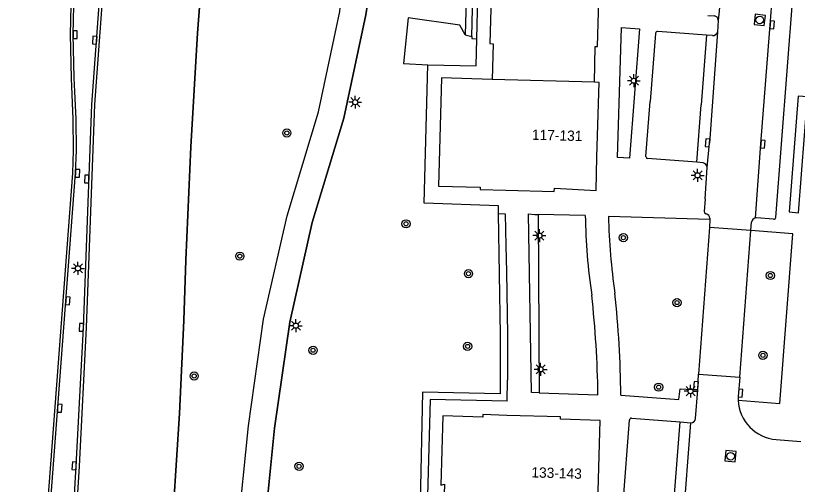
# Model space of a CAD drawing. Extents: x 132573 to 132944, y 398226 to 398676.
# Drawn here: x 132750.7 to 132826.8, y 398341.8 to 398387.4 of the extents above; entities that cross this region are included whole.
import ezdxf

# ---------------------------------------------------------------- set-up
doc = ezdxf.new("R2010")
doc.units = 0
for name, color, linetype in [('gg-anno-huisnummerreeks BGT', 7, 'Continuous'), ('gg-bbg-hoofdgebouw', 7, 'Continuous'), ('gg-bbg-tussenscheiding', 7, 'Continuous'), ('gg-knt-verharding', 7, 'Continuous'), ('gg-knt-verharding nz', 7, 'Continuous'), ('gt-grn-groengrens', 7, 'Continuous'), ('gt-symb-boom', 7, 'Continuous'), ('gt-symb-kolk', 7, 'Continuous'), ('gt-symb-lichtmast', 7, 'Continuous'), ('gt-symb-rioolschacht', 7, 'Continuous'), ('ir-asfa-asfalt arcering', 7, 'Continuous'), ('ir-asfa-asfalt rood', 7, 'Continuous')]:
    doc.layers.add(name, color=color, linetype=linetype)

msp = doc.modelspace()

# ---------------------------------------------------------------- linework, layer by layer
at = {"layer": 'gg-bbg-hoofdgebouw'}
msp.add_line((132807.26, 398337.57), (132807.56, 398348.04), dxfattribs=at)
for points in [[(132797.46, 398396.224), (132797.36, 398392.58), (132797.05, 398392.59), (132796.83, 398384.66), (132797.17, 398384.65), (132797.05, 398381.18)], [(132807.01, 398380.9), (132807.1, 398384.39), (132807.32, 398384.37), (132807.53, 398392.27), (132807.3, 398392.27), (132807.41, 398395.925)], [(132797.05, 398381.18), (132792.13, 398381.32), (132791.86, 398370.81), (132795.91, 398370.7), (132795.91, 398370.48), (132798.404, 398370.414)], [(132807.26, 398373.66), (132807.46, 398380.89), (132807.01, 398380.9)], [(132798.404, 398370.414), (132803.11, 398370.29), (132803.12, 398370.62), (132807.17, 398370.38), (132807.26, 398373.66)], [(132798.495, 398348.532), (132796.16, 398348.6), (132796.15, 398348.37), (132792.26, 398348.48), (132792.06, 398341.76), (132792.42, 398341.84), (132792.311, 398338)], [(132807.56, 398348.04), (132803.7, 398348.15), (132803.71, 398348.38), (132798.495, 398348.532)]]:
    msp.add_lwpolyline(points, dxfattribs=at)
at = {"layer": 'gg-bbg-tussenscheiding'}
msp.add_line((132807.01, 398380.9), (132797.05, 398381.18), dxfattribs=at)
at = {"layer": 'gg-knt-verharding'}
for p, q in [((132824.644, 398367.756), (132829.363, 398428.64)), ((132795.57, 398385.14), (132796.539, 398421.759)), ((132818.043, 398387.401), (132818.682, 398387.358)), ((132819.054, 398386.947), (132818.989, 398385.781)), ((132809.271, 398373.602), (132809.632, 398386.223)), ((132809.632, 398386.223), (132811.402, 398386.088)), ((132811.402, 398386.088), (132810.431, 398373.529)), ((132817.926, 398385.469), (132813.19, 398385.842)), ((132812.962, 398385.658), (132812.446, 398379.041)), ((132818.499, 398385.436), (132817.926, 398385.469)), ((132812.027, 398373.697), (132812.446, 398379.041)), ((132810.431, 398373.529), (132809.271, 398373.602)), ((132816.978, 398373.126), (132812.187, 398373.51)), ((132817.583, 398373.072), (132816.978, 398373.126)), ((132817.78, 398369.588), (132817.983, 398372.624)), ((132797.67, 398368.15), (132798.345, 398368.131)), ((132798.345, 398368.131), (132798.401, 398365.021)), ((132801.228, 398368.052), (132801.528, 398368.044)), ((132806.126, 398367.948), (132801.528, 398368.044)), ((132818.243, 398367.565), (132808.378, 398367.87)), ((132818.25, 398367.692), (132818.243, 398367.565)), ((132818.243, 398367.565), (132818.202, 398366.784)), ((132822.237, 398366.508), (132822.3, 398367.313)), ((132818.202, 398366.784), (132817.142, 398352.535)), ((132822.236, 398366.489), (132818.202, 398366.784)), ((132821.154, 398352.239), (132822.236, 398366.489)), ((132822.236, 398366.489), (132822.237, 398366.508)), ((132798.401, 398365.021), (132798.447, 398362.475)), ((132798.551, 398354.366), (132798.543, 398351.947)), ((132817.062, 398351.025), (132817.142, 398352.535)), ((132817.142, 398352.535), (132821.154, 398352.239)), ((132798.535, 398349.903), (132798.543, 398351.947)), ((132816.848, 398348.236), (132817.062, 398351.025)), ((132801.63, 398350.714), (132807.359, 398350.534)), ((132808.606, 398324.128), (132810.414, 398348.064)), ((132810.612, 398348.258), (132815.337, 398347.889)), ((132815.337, 398347.889), (132816.386, 398347.808)), ((132824.691, 398346.18), (132827.083, 398345.999))]:
    msp.add_line(p, q, dxfattribs=at)
for points in [[(132753.3, 398299.864), (132755.636, 398329.162), (132756.237, 398337.37), (132756.613, 398343.619), (132757.317, 398357.072), (132758.127, 398378.751), (132760.776, 398414.868), (132761.889, 398429.296), (132764.039, 398459.154), (132765.586, 398479.069)], [(132751.083, 398300.042), (132756.534, 398372.062), (132756.626, 398374.274), (132756.591, 398377.31), (132756.41, 398381.327), (132756.304, 398385.531), (132756.415, 398389.799), (132756.753, 398395.79), (132758.744, 398414.418), (132759.507, 398422.619), (132763.174, 398471.173), (132763.665, 398478.479)], [(132769.561, 398303.283), (132769.399, 398307.62), (132769.421, 398308.718), (132770.341, 398314.976), (132771.354, 398325.693), (132772.297, 398336.945), (132773.356, 398347.504), (132774.813, 398357.892), (132777.118, 398367.913), (132780.159, 398378.036), (132782.25, 398387.791), (132782.424, 398389.763), (132784.201, 398412.055), (132784.507, 398417.133), (132784.588, 398421.772), (132784.51, 398423.836), (132783.085, 398433.113), (132780.793, 398443.311), (132779.879, 398448.461), (132779.385, 398453.816)], [(132771.98, 398303.047), (132771.788, 398306.193), (132771.845, 398308.224), (132772.853, 398314.758), (132773.898, 398325.679), (132774.85, 398336.902), (132775.884, 398347.278), (132777.371, 398357.589), (132779.553, 398367.268), (132782.624, 398377.407), (132784.767, 398387.448), (132785.107, 398389.577), (132786.805, 398411.719), (132787.031, 398417.139), (132787.129, 398421.145)], [(132764.017, 398309.742), (132766.081, 398339.639), (132766.643, 398348.698), (132767.065, 398357.764), (132767.263, 398363.623), (132767.769, 398374.645), (132768.407, 398385.661), (132768.845, 398391.611)], [(132790.8, 398382.61), (132795.5, 398382.49), (132795.57, 398385.14)], [(132797.67, 398368.15), (132797.67, 398368.88), (132790.45, 398369.16), (132790.8, 398382.61)], [(132827.73, 398379.475), (132826.825, 398379.543), (132825.967, 398368.308)], [(132825.967, 398368.308), (132826.866, 398368.221), (132827.73, 398379.475)], [(132817.78, 398369.588), (132817.688, 398368.332), (132817.72, 398368.202), (132817.865, 398368.108)], [(132801.63, 398350.714), (132800.902, 398350.736), (132800.588, 398368.117), (132801.228, 398368.052)], [(132824.441, 398367.606), (132822.779, 398367.727), (132822.678, 398367.717)], [(132820.996, 398349.994), (132825.052, 398349.675), (132826.302, 398366.166), (132822.237, 398366.508)], [(132798.447, 398362.475), (132798.558, 398356.362), (132798.551, 398354.366)], [(132821.154, 398352.239), (132820.995, 398350.351), (132820.996, 398349.994)], [(132809.584, 398350.479), (132815.232, 398350.056), (132815.366, 398351.117), (132817.062, 398351.025)], [(132798.535, 398349.903), (132791.03, 398350.08), (132789.91, 398309.15), (132789.475, 398309.165)]]:
    msp.add_lwpolyline(points, dxfattribs=at)
for centre, radius, start, end in [((132818.609, 398386.918), 0.445, 3.66888, 80.62821), ((132813.14, 398385.671), 0.178, 73.54897, 184.25931), ((132818.492, 398385.967), 0.531, 270.80775, 339.48959), ((132812.215, 398373.696), 0.188, 179.64679, 261.4548), ((132817.479, 398372.576), 0.507, 5.41411, 78.10649), ((132865.478, 398368.846), 59.359, 180.86713, 188.37361), ((132871.93, 398369.413), 63.571, 181.39076, 188.13525), ((132817.783, 398367.646), 0.469, 5.62162, 79.94571), ((132822.77, 398367.252), 0.474, 101.1828, 172.62575), ((132824.479, 398367.767), 0.165, 256.70705, 356.21555), ((132704.278, 398348.915), 103.094, 0.89973, 6.28541), ((132704.129, 398349.258), 105.462, 0.66357, 6.07408), ((132825.011, 398350.187), 4.02, 182.75101, 265.43313), ((132810.609, 398348.063), 0.195, 89.01682, 179.81392), ((132816.401, 398348.255), 0.448, 268.11982, 357.50465)]:
    msp.add_arc(centre, radius, start, end, dxfattribs=at)
at = {"layer": 'gg-knt-verharding nz'}
for p, q in [((132817.926, 398385.469), (132817.4, 398378.71)), ((132818.989, 398385.781), (132818.215, 398374.995)), ((132816.978, 398373.126), (132817.4, 398378.71)), ((132817.983, 398372.624), (132818.215, 398374.995)), ((132813.517, 398323.528), (132815.337, 398347.889))]:
    msp.add_line(p, q, dxfattribs=at)
for points in [[(132822.678, 398367.717), (132823.197, 398374.914), (132825.235, 398400.952), (132826.312, 398415.022), (132826.738, 398420.929)], [(132819.912, 398397.905), (132819.149, 398387.801), (132819.054, 398386.947)], [(132814.506, 398323.009), (132815.632, 398338.083), (132816.386, 398347.808)]]:
    msp.add_lwpolyline(points, dxfattribs=at)
at = {"layer": 'gt-grn-groengrens'}
for p, q in [((132794.432, 398385.527), (132795.09, 398385.365)), ((132801.528, 398368.044), (132801.63, 398350.714)), ((132790.288, 398350.798), (132789.475, 398309.165))]:
    msp.add_line(p, q, dxfattribs=at)
for points in [[(132795.09, 398385.365), (132795.925, 398420.614), (132795.446, 398420.602), (132794.432, 398385.527)], [(132794.432, 398385.527), (132793.908, 398386.468), (132788.879, 398387.168), (132788.434, 398382.726), (132790.8, 398382.61)], [(132795.09, 398385.365), (132795.085, 398385.153), (132795.57, 398385.14)], [(132797.67, 398368.15), (132797.645, 398368.15), (132797.858, 398356.357), (132797.838, 398350.62), (132790.288, 398350.798)]]:
    msp.add_lwpolyline(points, dxfattribs=at)
at = {"layer": 'gt-symb-boom'}
for centre, radius in [((132777.095, 398375.978), 0.4), ((132777.095, 398375.978), 0.2), ((132788.685, 398367.144), 0.4), ((132788.685, 398367.144), 0.2), ((132809.831, 398365.806), 0.4), ((132809.831, 398365.806), 0.2), ((132772.519, 398364.006), 0.4), ((132772.519, 398364.006), 0.2), ((132794.76, 398362.3), 0.4), ((132794.76, 398362.3), 0.2), ((132824.122, 398362.126), 0.4), ((132824.122, 398362.126), 0.2), ((132815.05, 398359.491), 0.4), ((132815.05, 398359.491), 0.2), ((132794.673, 398355.232), 0.4), ((132794.673, 398355.232), 0.2), ((132779.648, 398354.856), 0.4), ((132779.648, 398354.856), 0.2), ((132823.399, 398354.369), 0.4), ((132823.399, 398354.369), 0.2), ((132768.079, 398352.353), 0.4), ((132768.079, 398352.353), 0.2), ((132813.257, 398351.271), 0.4), ((132813.257, 398351.271), 0.2), ((132778.283, 398343.574), 0.4), ((132778.283, 398343.574), 0.2)]:
    msp.add_circle(centre, radius, dxfattribs=at)
at = {"layer": 'gt-symb-kolk'}
for points in [[(132824.109, 398386.516), (132824.08, 398386.142), (132824.478, 398386.111), (132824.537, 398386.858), (132824.138, 398386.89), (132824.109, 398386.516)], [(132756.304, 398385.531), (132756.294, 398385.156), (132756.694, 398385.146), (132756.714, 398385.895), (132756.314, 398385.906), (132756.304, 398385.531)], [(132758.608, 398384.987), (132758.637, 398385.361), (132758.238, 398385.392), (132758.18, 398384.644), (132758.579, 398384.613), (132758.608, 398384.987)], [(132818.215, 398374.995), (132818.242, 398375.369), (132817.843, 398375.398), (132817.789, 398374.65), (132818.188, 398374.621), (132818.215, 398374.995)], [(132823.197, 398374.914), (132823.17, 398374.54), (132823.569, 398374.511), (132823.623, 398375.259), (132823.224, 398375.288), (132823.197, 398374.914)], [(132756.534, 398372.062), (132756.519, 398371.687), (132756.918, 398371.671), (132756.949, 398372.42), (132756.549, 398372.437), (132756.534, 398372.062)], [(132757.836, 398371.497), (132757.848, 398371.872), (132757.448, 398371.885), (132757.424, 398371.135), (132757.824, 398371.122), (132757.836, 398371.497)], [(132755.59, 398359.675), (132755.562, 398359.301), (132755.961, 398359.271), (132756.017, 398360.019), (132755.618, 398360.049), (132755.59, 398359.675)], [(132757.317, 398357.072), (132757.336, 398357.446), (132756.937, 398357.467), (132756.898, 398356.718), (132757.298, 398356.698), (132757.317, 398357.072)], [(132817.092, 398351.416), (132817.121, 398351.79), (132816.722, 398351.82), (132816.665, 398351.073), (132817.063, 398351.042), (132817.092, 398351.416)], [(132821.025, 398350.707), (132820.994, 398350.333), (132821.392, 398350.3), (132821.455, 398351.047), (132821.056, 398351.081), (132821.025, 398350.707)], [(132754.801, 398349.229), (132754.773, 398348.855), (132755.172, 398348.825), (132755.228, 398349.573), (132754.829, 398349.603), (132754.801, 398349.229)], [(132756.613, 398343.619), (132756.636, 398343.993), (132756.236, 398344.017), (132756.191, 398343.269), (132756.59, 398343.245), (132756.613, 398343.619)]]:
    msp.add_lwpolyline(points, dxfattribs=at)
at = {"layer": 'gt-symb-lichtmast'}
for p, q in [((132810.674, 398381.228), (132810.409, 398381.493)), ((132810.851, 398381.301), (132810.851, 398381.676)), ((132811.028, 398381.228), (132811.293, 398381.493)), ((132810.601, 398381.051), (132810.226, 398381.051)), ((132810.674, 398380.874), (132810.409, 398380.609)), ((132810.851, 398380.801), (132810.851, 398380.426)), ((132811.293, 398380.609), (132811.028, 398380.874)), ((132811.101, 398381.051), (132811.476, 398381.051)), ((132783.57, 398379.144), (132783.305, 398379.409)), ((132783.747, 398379.217), (132783.747, 398379.592)), ((132783.924, 398379.144), (132784.189, 398379.409)), ((132783.497, 398378.967), (132783.122, 398378.967)), ((132783.57, 398378.79), (132783.305, 398378.525)), ((132783.747, 398378.717), (132783.747, 398378.342)), ((132784.189, 398378.525), (132783.924, 398378.79)), ((132783.997, 398378.967), (132784.372, 398378.967)), ((132816.871, 398372.035), (132816.606, 398372.3)), ((132817.048, 398372.108), (132817.048, 398372.483)), ((132817.225, 398372.035), (132817.49, 398372.3)), ((132816.798, 398371.858), (132816.423, 398371.858)), ((132816.871, 398371.681), (132816.606, 398371.416)), ((132817.048, 398371.608), (132817.048, 398371.233)), ((132817.49, 398371.416), (132817.225, 398371.681)), ((132817.298, 398371.858), (132817.673, 398371.858)), ((132801.483, 398366.177), (132801.218, 398366.442)), ((132801.66, 398366.25), (132801.66, 398366.625)), ((132801.837, 398366.177), (132802.102, 398366.442)), ((132801.41, 398366), (132801.035, 398366)), ((132801.483, 398365.823), (132801.218, 398365.558)), ((132801.66, 398365.75), (132801.66, 398365.375)), ((132802.102, 398365.558), (132801.837, 398365.823)), ((132801.91, 398366), (132802.285, 398366)), ((132756.601, 398362.995), (132756.336, 398363.26)), ((132756.778, 398363.068), (132756.778, 398363.443)), ((132756.955, 398362.995), (132757.22, 398363.26)), ((132756.528, 398362.818), (132756.153, 398362.818)), ((132756.601, 398362.641), (132756.336, 398362.376)), ((132756.778, 398362.568), (132756.778, 398362.193)), ((132757.22, 398362.376), (132756.955, 398362.641)), ((132757.028, 398362.818), (132757.403, 398362.818)), ((132777.975, 398357.495), (132777.975, 398357.87)), ((132777.725, 398357.245), (132777.35, 398357.245)), ((132777.798, 398357.422), (132777.533, 398357.687)), ((132777.798, 398357.068), (132777.533, 398356.803)), ((132777.975, 398356.995), (132777.975, 398356.62)), ((132778.152, 398357.422), (132778.417, 398357.687)), ((132778.417, 398356.803), (132778.152, 398357.068)), ((132778.225, 398357.245), (132778.6, 398357.245)), ((132801.601, 398353.177), (132801.336, 398353.442)), ((132801.778, 398353.25), (132801.778, 398353.625)), ((132801.955, 398353.177), (132802.22, 398353.442)), ((132801.528, 398353), (132801.153, 398353)), ((132801.601, 398352.823), (132801.336, 398352.558)), ((132801.778, 398352.75), (132801.778, 398352.375)), ((132802.22, 398352.558), (132801.955, 398352.823)), ((132802.028, 398353), (132802.403, 398353)), ((132816.12, 398350.88), (132815.745, 398350.88)), ((132816.193, 398351.057), (132815.928, 398351.322)), ((132816.37, 398351.13), (132816.37, 398351.505)), ((132816.547, 398351.057), (132816.812, 398351.322)), ((132816.62, 398350.88), (132816.995, 398350.88)), ((132816.193, 398350.703), (132815.928, 398350.438)), ((132816.37, 398350.63), (132816.37, 398350.255)), ((132816.812, 398350.438), (132816.547, 398350.703))]:
    msp.add_line(p, q, dxfattribs=at)
for centre in [(132810.851, 398381.051), (132783.747, 398378.967), (132817.048, 398371.858), (132801.66, 398366), (132756.778, 398362.818), (132777.975, 398357.245), (132801.778, 398353), (132816.37, 398350.88)]:
    msp.add_circle(centre, 0.25, dxfattribs=at)
at = {"layer": 'gt-symb-rioolschacht'}
for points in [[(132823.53, 398386.408), (132823.655, 398387.401), (132822.662, 398387.526), (132822.537, 398386.533)], [(132819.706, 398344.109), (132820.701, 398344.006), (132820.804, 398345.001), (132819.809, 398345.104)]]:
    msp.add_lwpolyline(points, close=True, dxfattribs=at)
for centre in [(132823.096, 398386.967), (132820.255, 398344.555)]:
    msp.add_circle(centre, 0.375, dxfattribs=at)
at = {"layer": 'ir-asfa-asfalt arcering'}
for points in [[(132756.536, 398337.35), (132756.913, 398343.602), (132757.617, 398357.059), (132758.427, 398378.734), (132761.075, 398414.845), (132762.188, 398429.274), (132764.338, 398459.132)], [(132772.884, 398446.484), (132769.392, 398399.047), (132768.845, 398391.611), (132768.407, 398385.661), (132767.769, 398374.645), (132767.263, 398363.623), (132767.065, 398357.764), (132766.643, 398348.698), (132766.081, 398339.639)], [(132745.571, 398382.431), (132746.483, 398387.846), (132747.325, 398393.731), (132756.281, 398392.746), (132756.115, 398389.811), (132756.004, 398385.531), (132756.11, 398381.316), (132756.291, 398377.302), (132756.326, 398374.279), (132756.234, 398372.08), (132750.784, 398300.065), (132750.784, 398300.061), (132750.599, 398297.174), (132750.599, 398297.173), (132737.591, 398297.947)]]:
    msp.add_lwpolyline(points, dxfattribs=at)
at = {"layer": 'ir-asfa-asfalt rood'}
msp.add_lwpolyline([(132772.297, 398336.945), (132773.356, 398347.504), (132774.813, 398357.892), (132777.118, 398367.913), (132780.159, 398378.036), (132782.25, 398387.791), (132782.424, 398389.763), (132782.433, 398389.871), (132785.107, 398389.577), (132784.767, 398387.448), (132782.624, 398377.407), (132779.553, 398367.268), (132777.371, 398357.589), (132775.884, 398347.278), (132774.85, 398336.902)], dxfattribs=at)

# ---------------------------------------------------------------- texts
at = {"layer": 'gg-anno-huisnummerreeks BGT'}
for s, rotation, p in [('117-131', 358.4, (132800.922, 398375.316)), ('133-143', 358.3, (132800.868, 398342.5))]:
    msp.add_text(s, height=1, rotation=rotation, dxfattribs=at).set_placement(p)

doc.saveas('drawing.dxf')
